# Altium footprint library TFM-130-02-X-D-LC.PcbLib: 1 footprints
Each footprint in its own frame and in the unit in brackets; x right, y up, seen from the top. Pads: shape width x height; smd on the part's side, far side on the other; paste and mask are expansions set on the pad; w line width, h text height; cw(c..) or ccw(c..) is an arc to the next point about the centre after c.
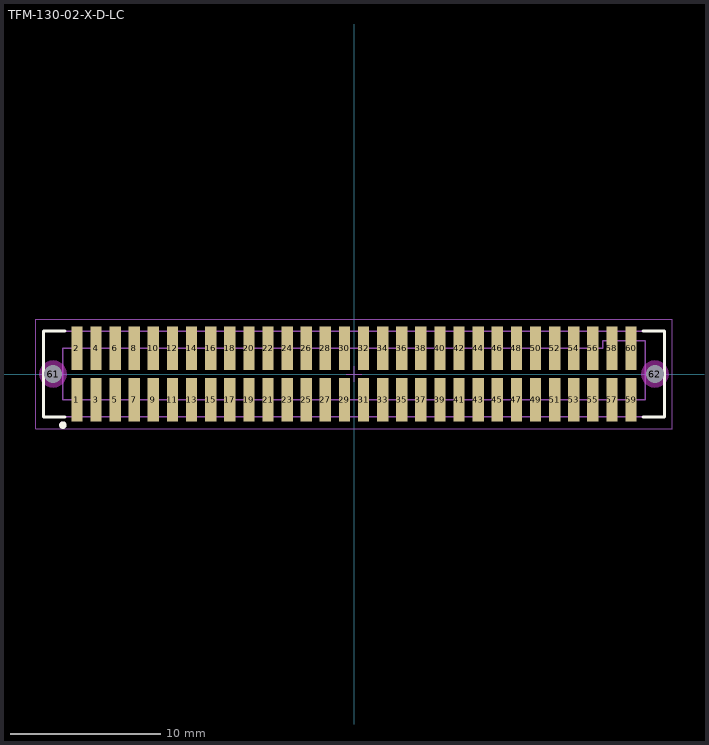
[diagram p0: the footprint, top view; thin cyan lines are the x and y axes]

## TFM-130-02-X-D-LC [mm] "1.27mm pitch, 60 pin, terminal header; w/alignment pins, SMT"
height 5.72
pads (62):
  rect 0.75x2.9 smd mask+0: 1(-18.415,-1.714) 2(-18.415,1.714) 3(-17.145,-1.714) 4(-17.145,1.714) 5(-15.875,-1.714) 6(-15.875,1.714) 7(-14.605,-1.714) 8(-14.605,1.714) 9(-13.335,-1.714) 10(-13.335,1.714) 11(-12.065,-1.714) 12(-12.065,1.714) 13(-10.795,-1.714) 14(-10.795,1.714) 15(-9.525,-1.714) 16(-9.525,1.714) 17(-8.255,-1.714) 18(-8.255,1.714) 19(-6.985,-1.714) 20(-6.985,1.714) 21(-5.715,-1.714) 22(-5.715,1.714) 23(-4.445,-1.714) 24(-4.445,1.714) 25(-3.175,-1.714) 26(-3.175,1.714) 27(-1.905,-1.714) 28(-1.905,1.714) 29(-0.635,-1.714) 30(-0.635,1.714) 31(0.635,-1.714) 32(0.635,1.714) 33(1.905,-1.714) 34(1.905,1.714) 35(3.175,-1.714) 36(3.175,1.714) 37(4.445,-1.714) 38(4.445,1.714) 39(5.715,-1.714) 40(5.715,1.714) 41(6.985,-1.714) 42(6.985,1.714) 43(8.255,-1.714) 44(8.255,1.714) 45(9.525,-1.714) 46(9.525,1.714) 47(10.795,-1.714) 48(10.795,1.714) 49(12.065,-1.714) 50(12.065,1.714) 51(13.335,-1.714) 52(13.335,1.714) 53(14.605,-1.714) 54(14.605,1.714) 55(15.875,-1.714) 56(15.875,1.714) 57(17.145,-1.714) 58(17.145,1.714) 59(18.415,-1.714) 60(18.415,1.714)
  round 1 hole 1.2 unplated mask+0: 61(-20.002,0) 62(20.002,0)
Top Overlay:
  circle w0.25: c-19.35,-3.4 r0.125
  lines w0.2: -19.2,-2.85 -20.65,-2.85 -20.65,2.85 -19.2,2.85 ; 19.2,-2.85 20.65,-2.85 20.65,2.85 19.2,2.85
Keep-Out Layer:
  pour cut-out: 20.91,0 20.88,0.235 20.789,0.454 20.645,0.642 20.457,0.786 20.238,0.877 20.003,0.908 19.768,0.877 19.549,0.786 19.361,0.642 19.217,0.454 19.126,0.235 19.095,0 19.126,-0.235 19.217,-0.454 19.361,-0.642 19.549,-0.786 19.768,-0.877 20.003,-0.908 20.238,-0.877 20.457,-0.786 20.645,-0.642 20.789,-0.454 20.88,-0.235
  pour cut-out: -19.095,0 -19.126,0.235 -19.217,0.454 -19.361,0.642 -19.549,0.786 -19.768,0.877 -20.003,0.908 -20.238,0.877 -20.457,0.786 -20.645,0.642 -20.789,0.454 -20.88,0.235 -20.91,0 -20.88,-0.235 -20.789,-0.454 -20.645,-0.642 -20.457,-0.786 -20.238,-0.877 -20.003,-0.908 -19.768,-0.877 -19.549,-0.786 -19.361,-0.642 -19.217,-0.454 -19.126,-0.235
Mechanical 12:
  lines w0.001: -20.65,-2.85 20.65,-2.85 20.65,2.85 -20.65,2.85 -20.65,-2.85 ; -19.35,-1.7 19.35,-1.7 19.35,2.2 16.55,2.2 16.55,1.7 -19.35,1.7 -19.35,-1.7
Mechanical 13:
  circle w0.1: c-19.416,-3.35 r0.127
  lines w0.1: -20.65,-2.85 20.65,-2.85 20.65,2.85 -20.65,2.85 -20.65,-2.85 ; -19.35,-1.7 19.35,-1.7 19.35,2.2 16.55,2.2 16.55,1.7 -19.35,1.7 -19.35,-1.7
  text ".Designator" at 0,-0.127 h1.52
Mechanical 15:
  lines w0.05: -0.5,0 0.5,0 ; 0,-0.5 0,0.5 ; -21.15,-3.65 21.15,-3.65 21.15,3.65 -21.15,3.65 -21.15,-3.65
